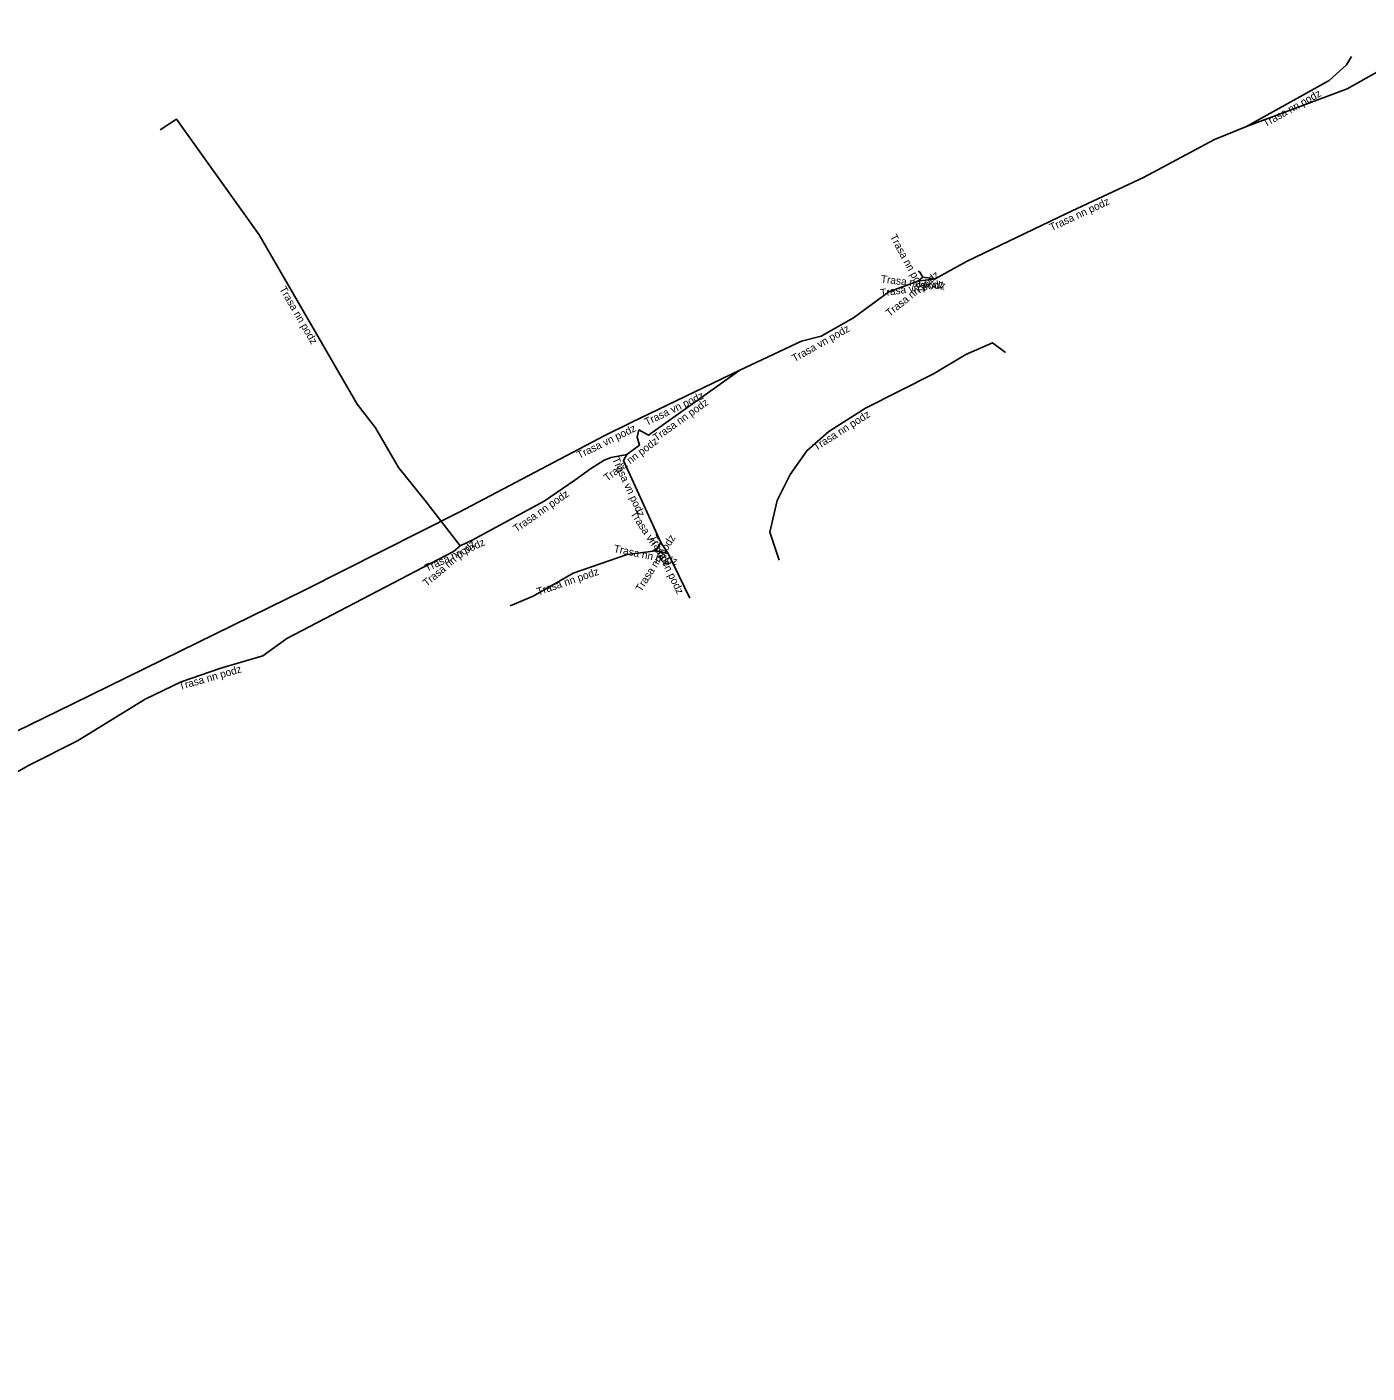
# Model space of a CAD drawing. Extents: x -691765 to -691141, y -976282 to -975901.
# Drawn here: x -691552 to -691463.6, y -976172.4 to -976083.6 of the extents above; entities that cross this region are included whole.
import ezdxf

# ---------------------------------------------------------------- set-up
doc = ezdxf.new("R2010")
doc.units = 0
for name, color, linetype in [('Popiskový text - Ostatní atributy Trasy', 7, 'Continuous'), ('Spojnice NN', 7, 'Continuous'), ('Spojnice VN', 7, 'Continuous')]:
    doc.layers.add(name, color=color, linetype=linetype)

msp = doc.modelspace()

# ---------------------------------------------------------------- linework, layer by layer
at = {"layer": 'Spojnice NN'}
for points in [[(-691471.57, -976090.22), (-691466.13, -976087.17), (-691464.98, -976086.15), (-691464.65, -976085.59)], [(-691543.23, -976090.44), (-691542.15, -976089.72), (-691536.7, -976097.35), (-691530.22, -976108.53), (-691529.01, -976110.09), (-691527.51, -976112.7), (-691525.77, -976114.85), (-691523.43, -976117.86)], [(-691492.1, -976100.25), (-691490.03, -976099.11), (-691483.39, -976095.92), (-691478.36, -976093.58), (-691473.68, -976091.08), (-691471.57, -976090.22)], [(-691492.92, -976100.16), (-691493.24, -976100.42)], [(-691492.92, -976100.16), (-691493.11, -976099.81), (-691493.22, -976099.76)], [(-691492.1, -976100.25), (-691492.92, -976100.16)], [(-691502.39, -976118.81), (-691503, -976116.96), (-691502.53, -976114.88), (-691501.66, -976113.17), (-691500.58, -976111.6), (-691499.13, -976110.32), (-691496.71, -976108.78), (-691492.22, -976106.52), (-691490.09, -976105.25), (-691488.32, -976104.49), (-691487.47, -976105.11)], [(-691511.65, -976110.22), (-691511.02, -976110.57), (-691505, -976106.29)], [(-691512.44, -976111.85), (-691511.61, -976111.22), (-691511.75, -976110.7), (-691511.65, -976110.22)], [(-691512.44, -976111.85), (-691513.48, -976112.05), (-691513.93, -976112.21), (-691514.84, -976112.79), (-691515.88, -976113.53), (-691517.89, -976114.93), (-691522.65, -976117.5)], [(-691523.88, -976118.24), (-691523.43, -976117.86)], [(-691522.65, -976117.5), (-691523.43, -976117.86)], [(-691510.53, -976118.2), (-691510.19, -976117.66)], [(-691523.88, -976118.24), (-691534.87, -976123.97), (-691536.44, -976125.13), (-691539.21, -976125.93), (-691541.84, -976126.83), (-691544.21, -976127.98), (-691548.67, -976130.73), (-691551.86, -976132.33), (-691554.22, -976133.66)], [(-691520.14, -976121.82), (-691518.62, -976121.18), (-691515.98, -976119.67), (-691512.42, -976118.45), (-691510.53, -976118.2)], [(-691510.53, -976118.2), (-691509.72, -976118.37)]]:
    msp.add_lwpolyline(points, dxfattribs=at)
at = {"layer": 'Spojnice VN'}
for points in [[(-691471.57, -976090.22), (-691464.94, -976087.72), (-691448.05, -976078.23), (-691441.15, -976074.11), (-691437.4, -976070.71), (-691426.21, -976064.35), (-691422.65, -976063.48), (-691420.39, -976063.16), (-691418.17, -976062.71), (-691404.31, -976054.99), (-691390.35, -976046.8), (-691389.87, -976046.44), (-691388.972, -976045.605), (-691382.956, -976041.512), (-691374.973, -976036.206), (-691370.63, -976033.74), (-691369.13, -976033.69), (-691362.44, -976029.7), (-691353.78, -976024.29), (-691341.56, -976016.46)], [(-691505, -976106.29), (-691500.93, -976104.38), (-691499.63, -976104.03), (-691497.5, -976102.83), (-691495.17, -976101.11), (-691493.24, -976100.42)], [(-691492.1, -976100.25), (-691493.24, -976100.42)], [(-691505, -976106.29), (-691512.15, -976109.73)], [(-691512.15, -976109.73), (-691513.94, -976110.61)], [(-691619.85, -976172.43), (-691616.99, -976170.64), (-691615.85, -976169.55), (-691614.99, -976168.01), (-691603, -976160.37), (-691594.79, -976154.85), (-691594.15, -976154.48), (-691591.37, -976153.98), (-691587.54, -976151.61), (-691573.45, -976142.15), (-691567, -976138.54), (-691555.53, -976131.47), (-691548.99, -976128.3), (-691533.7, -976120.79), (-691523.51, -976115.65), (-691513.94, -976110.61)], [(-691510.19, -976117.66), (-691512.67, -976112.25), (-691512.44, -976111.85)], [(-691510.19, -976117.66), (-691509.72, -976118.37)], [(-691509.72, -976118.37), (-691508.28, -976121.31)]]:
    msp.add_lwpolyline(points, dxfattribs=at)

# ---------------------------------------------------------------- texts
at = {"layer": 'Popiskový text - Ostatní atributy Trasy'}
for s, rotation, p in [('Trasa nn podz', 29.27768, (-691470.323, -976090.266)), ('Trasa nn podz', 24.94826, (-691484.427, -976097.119)), ('Trasa nn podz', 298.49564, (-691495.116, -976097.476)), ('Trasa nn podz', 353.73651, (-691495.71, -976100.508)), ('Trasa nn podz', 39.09386, (-691495.113, -976102.779)), ('Trasa nn podz', 300.09686, (-691535.378, -976100.927)), ('Trasa vn podz', 8.48161, (-691495.687, -976101.443)), ('Trasa vn podz', 29.39605, (-691501.379, -976105.762)), ('Trasa vn podz', 25.69309, (-691511.13, -976109.96)), ('Trasa nn podz', 35.41144, (-691510.493, -976110.993)), ('Trasa nn podz', 32.47119, (-691499.954, -976111.615)), ('Trasa vn podz', 26.17966, (-691515.583, -976112.142)), ('Trasa nn podz', 37.19981, (-691513.729, -976113.645)), ('Trasa vn podz', 294.62721, (-691513.429, -976112.155)), ('Trasa nn podz', 34.85788, (-691519.719, -976116.996)), ('Trasa vn podz', 303.50344, (-691512.235, -976115.749)), ('Trasa nn podz', 40.17923, (-691525.641, -976120.578)), ('Trasa nn podz', 24.77514, (-691525.625, -976119.589)), ('Trasa nn podz', 348.147, (-691513.339, -976118.274)), ('Trasa nn podz', 57.80427, (-691511.488, -976120.94)), ('Trasa vn podz', 296.09542, (-691510.968, -976117.299)), ('Trasa nn podz', 18.91641, (-691518.284, -976121.147)), ('Trasa nn podz', 16.10918, (-691541.911, -976127.387))]:
    msp.add_text(s, height=0.5, rotation=rotation, dxfattribs=at).set_placement(p)

doc.saveas('drawing.dxf')
